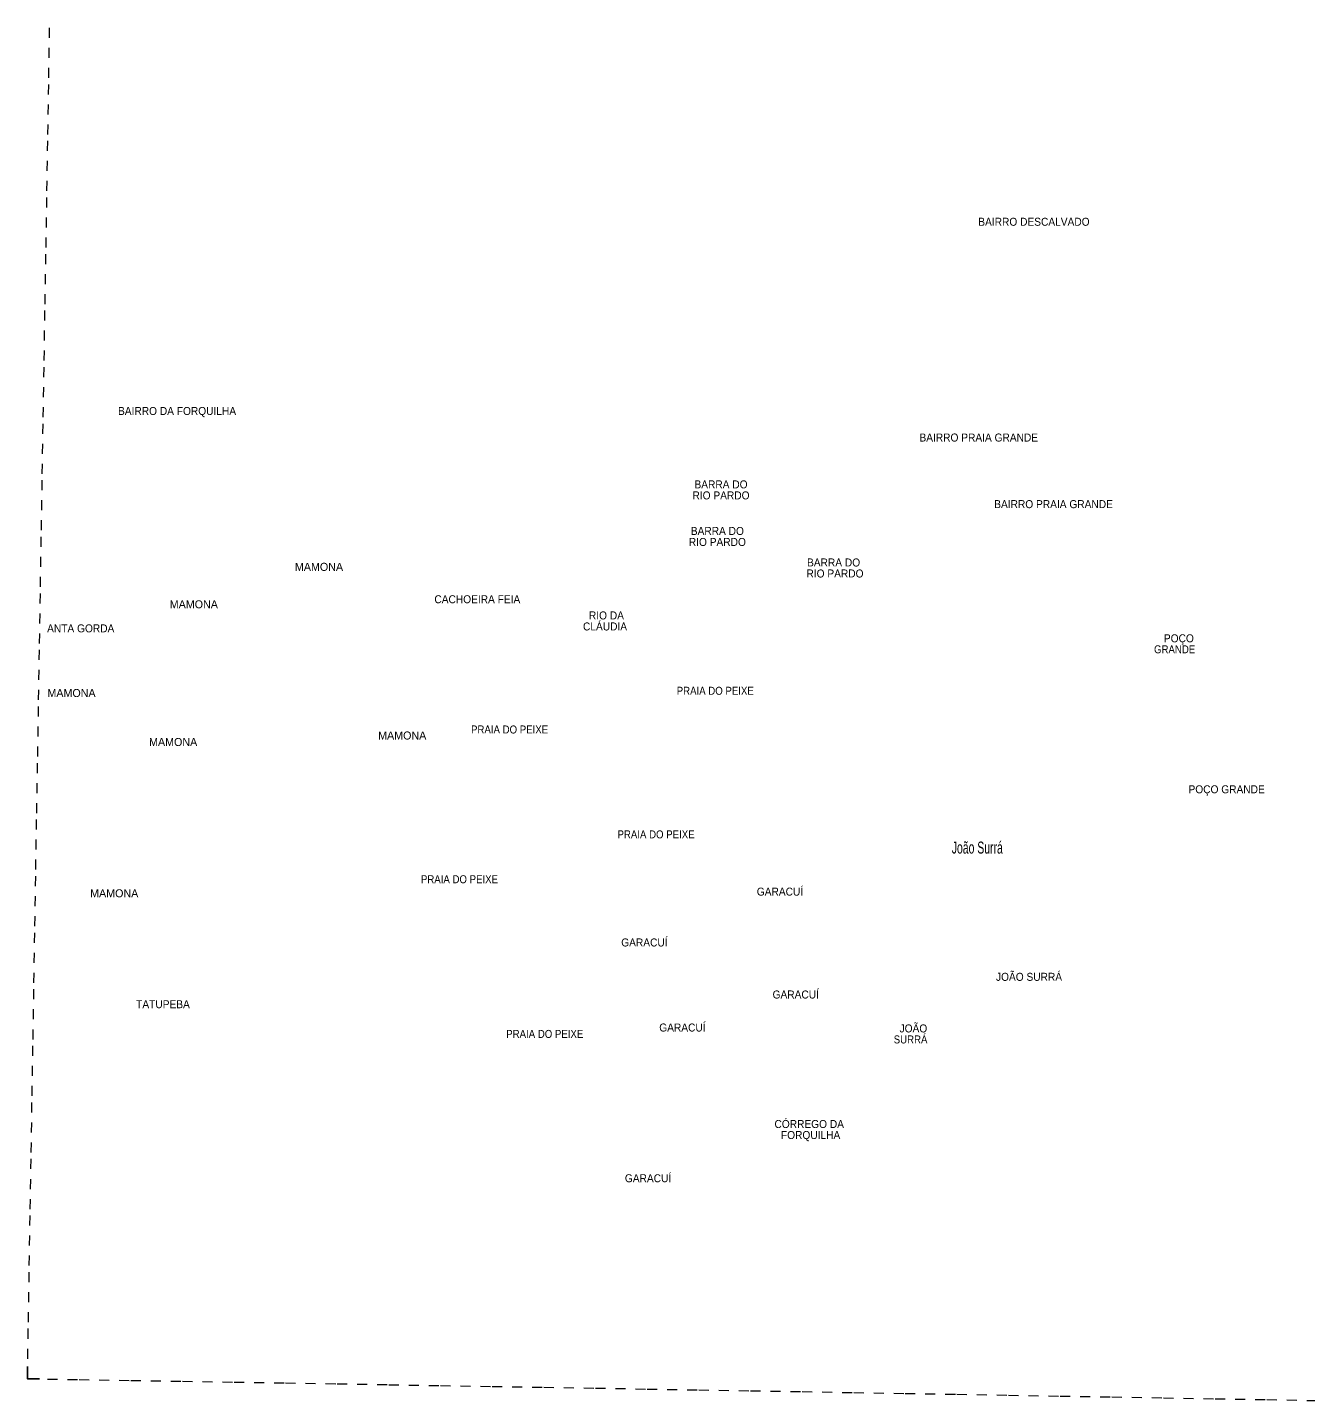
# Model space of a CAD drawing. Extents: x 727.5 to 753.3, y 7260.4 to 7288.5.
# Drawn here: x 727.54 to 740.32, y 7260.64 to 7274.36 of the extents above; entities that cross this region are included whole.
import ezdxf
from ezdxf.enums import TextEntityAlignment as Align

# ---------------------------------------------------------------- set-up
doc = ezdxf.new("R2010")
doc.units = 0
doc.header["$LTSCALE"] = 0.032
doc.linetypes.add('SHORT_DASHED', pattern=[2.7, 1.5, -1.2])
doc.layers.add('46', color=7, linetype='SHORT_DASHED', lineweight=13)
doc.layers.add('63', color=7, linetype='Continuous', lineweight=25)
doc.layers.add('61', color=7, linetype='Continuous')

msp = doc.modelspace()

# ---------------------------------------------------------------- linework, layer by layer
at = {"layer": '46'}
for points in [[(727.5431, 7260.8533), (727.5524, 7261.4185), (727.5617, 7261.9837), (727.571, 7262.5489), (727.5803, 7263.1141), (727.5896, 7263.6793), (727.5989, 7264.2445), (727.6082, 7264.8097), (727.6174, 7265.375), (727.6267, 7265.9402), (727.636, 7266.5054), (727.6453, 7267.0706), (727.6546, 7267.6358), (727.6638, 7268.201), (727.6731, 7268.7662), (727.6824, 7269.3314), (727.6917, 7269.8966), (727.7009, 7270.4618), (727.7102, 7271.027), (727.7195, 7271.5922), (727.7287, 7272.1574), (727.738, 7272.7226), (727.7472, 7273.2878), (727.7565, 7273.853), (727.7657, 7274.4182)], [(727.5431, 7260.8533), (728.0593, 7260.8448), (728.5754, 7260.8363), (729.0916, 7260.8277), (729.6077, 7260.8192), (730.1239, 7260.8106), (730.64, 7260.802), (731.1562, 7260.7934), (731.6723, 7260.7847), (732.1885, 7260.7761), (732.7046, 7260.7674), (733.2208, 7260.7587), (733.7369, 7260.75), (734.2531, 7260.7413), (734.7693, 7260.7325), (735.2854, 7260.7238), (735.8016, 7260.715), (736.3178, 7260.7062), (736.8339, 7260.6973), (737.3501, 7260.6885), (737.8663, 7260.6796), (738.3824, 7260.6707), (738.8986, 7260.6618), (739.4148, 7260.6529), (739.9309, 7260.644), (740.4471, 7260.635)]]:
    msp.add_lwpolyline(points, dxfattribs=at)
at = {"layer": '63'}
msp.add_lwpolyline([(727.5431, 7260.9765), (727.5431, 7260.8533), (727.6645, 7260.8533)], dxfattribs=at)

# ---------------------------------------------------------------- texts
at = {"layer": '61'}
for s, width, p in [('BAIRRO DESCALVADO', 0.95, (737.60345, 7272.3748)), ('BAIRRO DA FORQUILHA', 0.95, (729.0385, 7270.4838)), ('BAIRRO PRAIA GRANDE', 0.95, (737.052, 7270.2185)), ('BARRA DO', 0.95, (734.47555, 7269.7502)), ('RIO PARDO', 0.95, (734.4756, 7269.6402)), ('BAIRRO PRAIA GRANDE', 0.95, (737.7995, 7269.553)), ('BARRA DO', 0.95, (734.43905, 7269.285)), ('RIO PARDO', 0.95, (734.4391, 7269.175)), ('RIO PARDO', 0.95, (735.615, 7268.8598)), ('BARRA DO ', 0.95, (735.61495, 7268.9698)), ('CACHOEIRA FEIA', 0.95, (732.03985, 7268.6023)), ('  RIO DA ', 0.95, (733.3162, 7268.4407)), ('ANTA GORDA', 0.95, (728.07565, 7268.3114)), ('CLÁUDIA', 0.95, (733.31625, 7268.3307)), ('   POÇO', 0.95, (739.00975, 7268.2121)), ('GRANDE', 0.9, (739.0097, 7268.1021)), ('PRAIA DO PEIXE', 0.9, (734.418, 7267.6878)), ('PRAIA DO PEIXE', 0.9, (732.3623, 7267.301)), ('POÇO GRANDE', 0.95, (739.52965, 7266.7032)), ('PRAIA DO PEIXE', 0.9, (733.8263, 7266.2527)), ('PRAIA DO PEIXE', 0.9, (731.8612, 7265.8043)), ('GARACUÍ', 0.95, (735.0649, 7265.6805)), ('GARACUÍ', 0.95, (733.7098, 7265.1727)), ('JOÃO SURRÁ', 0.95, (737.5544, 7264.8292)), ('GARACUÍ', 0.95, (735.2227, 7264.6526)), ('TATUPEBA', 0.95, (728.898, 7264.5553)), ('GARACUÍ', 0.95, (734.0899, 7264.3226)), ('  JOÃO', 0.95, (736.3705, 7264.3136)), ('PRAIA DO PEIXE', 0.9, (732.714, 7264.2586)), ('SURRÁ', 0.9, (736.3705, 7264.2036)), ('CÓRREGO DA', 0.95, (735.35725, 7263.3584)), (' FORQUILHA', 0.95, (735.35715, 7263.2484)), ('GARACUÍ', 0.95, (733.7462, 7262.8162))]:
    msp.add_text(s, height=0.08, dxfattribs=dict(at, width=width)).set_placement(p, align=Align.CENTER)
for p in [(730.45715, 7268.9262), (729.20625, 7268.552), (727.98355, 7267.6654), (731.28905, 7267.2407), (728.99945, 7267.1759), (728.41035, 7265.664)]:
    msp.add_text('MAMONA', height=0.08, dxfattribs=at).set_placement(p, align=Align.CENTER)
at = {"layer": '61', "width": 0.65}
msp.add_text('João Surrá', height=0.12, dxfattribs=at).set_placement((736.7821, 7266.1008))

doc.saveas('drawing.dxf')
